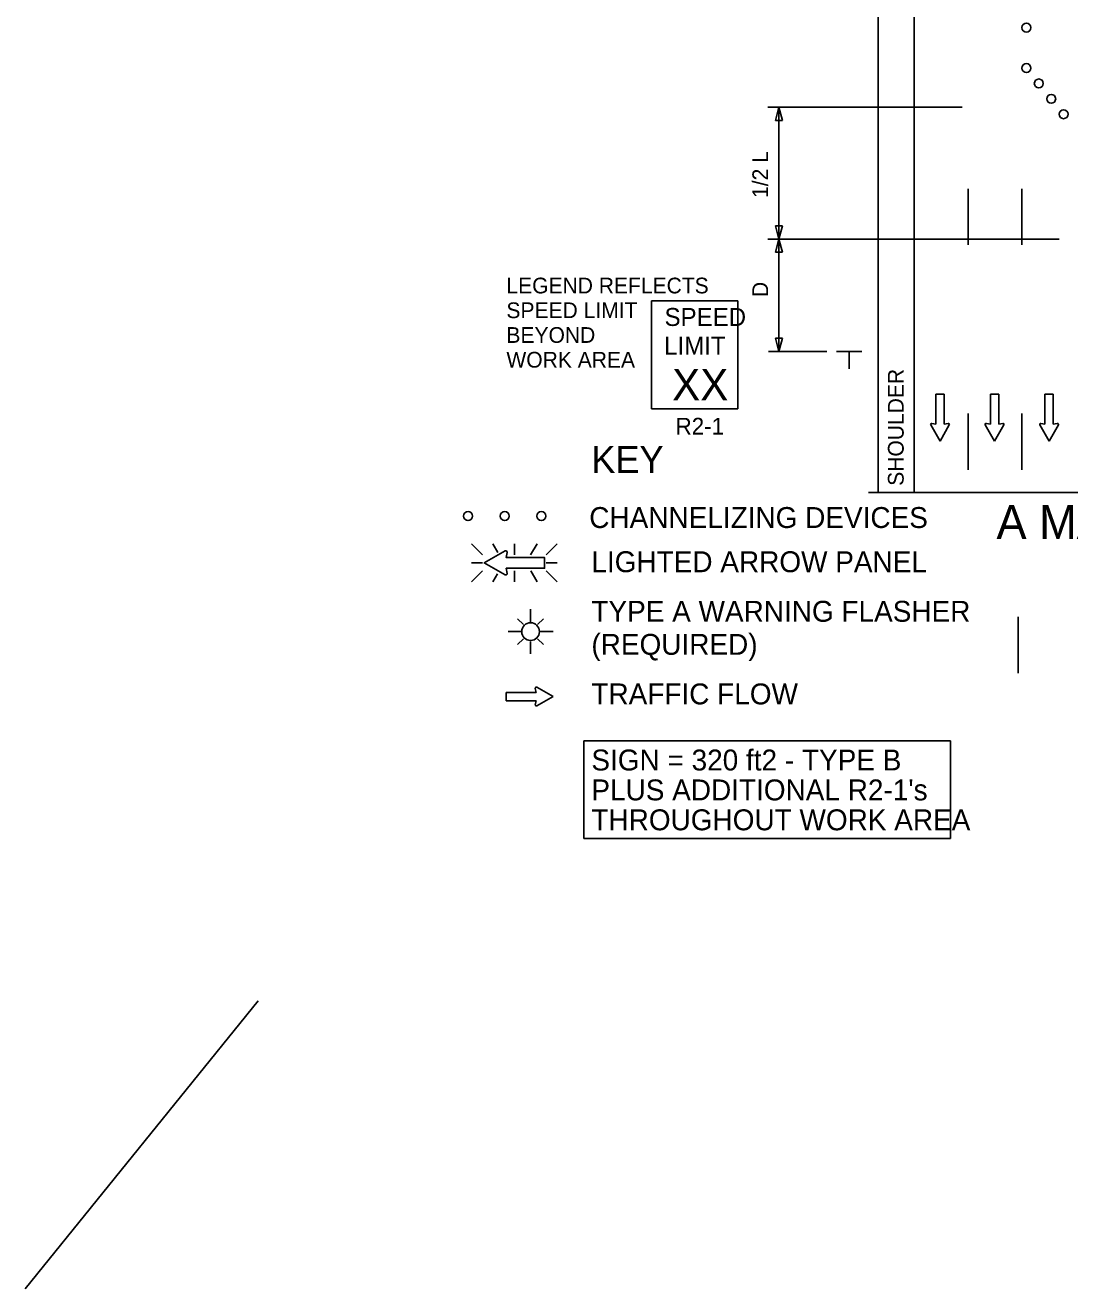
# Model space of a CAD drawing. Extents: x 16544 to 19504, y 5662 to 6909.
# Drawn here: x 16544 to 17009, y 5752 to 6314 of the extents above; entities that cross this region are included whole.
import ezdxf

# ---------------------------------------------------------------- set-up
doc = ezdxf.new("R2010")
doc.units = 0
for name, color, linetype in [('ALI_LEGAL_EX', 7, 'Continuous'), ('MT_SCRATCH_LEVEL_E', 7, 'Continuous'), ('PAVT_EDGE_EX', 7, 'Continuous'), ('TRAFFIC_SIGNS_PR', 7, 'Continuous'), ('TYPICAL_TEXT_DIMEN_EX', 7, 'Continuous'), ('TYPICAL_TEXT_DIMEN_PR', 7, 'Continuous')]:
    doc.layers.add(name, color=color, linetype=linetype)

msp = doc.modelspace()

# ---------------------------------------------------------------- linework, layer by layer
at = {"layer": 'ALI_LEGAL_EX'}
for points in [[(16963.46, 6241.23), (16963.46, 6216.23)], [(16987.46, 6241.23), (16987.46, 6216.23)], [(16963.46, 6141.23), (16963.46, 6116.23)], [(16987.46, 6141.23), (16987.46, 6116.23)]]:
    msp.add_lwpolyline(points, dxfattribs=at)
at = {"layer": 'MT_SCRATCH_LEVEL_E'}
for p, q in [((16952.87, 6149.79), (16949.13, 6149.79)), ((16949.13, 6149.79), (16949.13, 6136.54)), ((16952.87, 6149.79), (16949.13, 6149.79)), ((16949.13, 6149.79), (16949.13, 6136.54)), ((16952.87, 6136.54), (16952.87, 6149.79)), ((16952.87, 6136.54), (16952.87, 6149.79)), ((16977.13, 6149.79), (16973.39, 6149.79)), ((16973.39, 6149.79), (16973.39, 6136.54)), ((16977.13, 6149.79), (16973.39, 6149.79)), ((16973.39, 6149.79), (16973.39, 6136.54)), ((16977.13, 6136.54), (16977.13, 6149.79)), ((16977.13, 6136.54), (16977.13, 6149.79)), ((17001.39, 6149.79), (16997.64, 6149.79)), ((16997.64, 6149.79), (16997.64, 6136.54)), ((17001.39, 6149.79), (16997.64, 6149.79)), ((16997.64, 6149.79), (16997.64, 6136.54)), ((17001.39, 6136.54), (17001.39, 6149.79)), ((17001.39, 6136.54), (17001.39, 6149.79)), ((16946.87, 6136.17), (16951.02, 6128.93)), ((16946.87, 6136.17), (16951.02, 6128.93)), ((16949.13, 6136.54), (16947.35, 6136.85)), ((16949.13, 6136.54), (16947.35, 6136.85)), ((16951.02, 6128.93), (16955.13, 6136.17)), ((16951.02, 6128.93), (16955.13, 6136.17)), ((16954.65, 6136.85), (16952.87, 6136.54)), ((16954.65, 6136.85), (16952.87, 6136.54)), ((16971.13, 6136.17), (16975.28, 6128.93)), ((16971.13, 6136.17), (16975.28, 6128.93)), ((16973.39, 6136.54), (16971.61, 6136.85)), ((16973.39, 6136.54), (16971.61, 6136.85)), ((16975.28, 6128.93), (16979.39, 6136.17)), ((16975.28, 6128.93), (16979.39, 6136.17)), ((16978.91, 6136.85), (16977.13, 6136.54)), ((16978.91, 6136.85), (16977.13, 6136.54)), ((16995.39, 6136.17), (16999.53, 6128.93)), ((16995.39, 6136.17), (16999.53, 6128.93)), ((16997.64, 6136.54), (16995.87, 6136.85)), ((16997.64, 6136.54), (16995.87, 6136.85)), ((16999.53, 6128.93), (17003.64, 6136.17)), ((16999.53, 6128.93), (17003.64, 6136.17)), ((17003.16, 6136.85), (17001.39, 6136.54)), ((17003.16, 6136.85), (17001.39, 6136.54)), ((16778.89, 6015.35), (16771.65, 6019.46)), ((16778.89, 6015.35), (16771.65, 6019.46)), ((16771.28, 6017.2), (16758.03, 6017.2)), ((16758.03, 6017.2), (16758.03, 6013.46)), ((16771.28, 6017.2), (16758.03, 6017.2)), ((16758.03, 6017.2), (16758.03, 6013.46)), ((16770.97, 6018.98), (16771.28, 6017.2)), ((16770.97, 6018.98), (16771.28, 6017.2)), ((16771.65, 6011.21), (16778.89, 6015.35)), ((16771.65, 6011.21), (16778.89, 6015.35)), ((16758.03, 6013.46), (16771.28, 6013.46)), ((16758.03, 6013.46), (16771.28, 6013.46)), ((16771.28, 6013.46), (16770.97, 6011.69)), ((16771.28, 6013.46), (16770.97, 6011.69))]:
    msp.add_line(p, q, dxfattribs=at)
for centre, start, end in [((16947.28, 6136.39), 80.0362, 209.7731), ((16947.28, 6136.39), 80.0362, 209.7731), ((16954.72, 6136.39), 330.4248, 99.9638), ((16954.72, 6136.39), 330.4248, 99.9638), ((16971.54, 6136.39), 80.0362, 209.7731), ((16971.54, 6136.39), 80.0362, 209.7731), ((16978.98, 6136.39), 330.4248, 99.9638), ((16978.98, 6136.39), 330.4248, 99.9638), ((16995.8, 6136.39), 80.0362, 209.7731), ((16995.8, 6136.39), 80.0362, 209.7731), ((17003.24, 6136.39), 330.4248, 99.9638), ((17003.24, 6136.39), 330.4248, 99.9638), ((16771.43, 6019.06), 60.4248, 189.9638), ((16771.43, 6019.06), 60.4248, 189.9638), ((16771.43, 6011.62), 170.0362, 299.7731), ((16771.43, 6011.62), 170.0362, 299.7731)]:
    msp.add_arc(centre, 0.463, start, end, dxfattribs=at)
at = {"layer": 'PAVT_EDGE_EX'}
for p, q in [((16923.46, 6880.02), (16923.46, 6106.05)), ((16939.46, 6880.02), (16939.46, 6106.05))]:
    msp.add_line(p, q, dxfattribs=at)
msp.add_lwpolyline([(16985.78, 6025.74), (16985.78, 6050.74)], dxfattribs=at)
msp.add_lwpolyline([(16985.78, 6025.74), (16985.78, 6050.74)], dxfattribs=at)
at = {"layer": 'TRAFFIC_SIGNS_PR'}
for p, q in [((16822.7, 6191.31), (16861.1, 6191.31)), ((16822.7, 6143.31), (16822.7, 6191.31)), ((16861.1, 6143.31), (16861.1, 6191.31)), ((16822.7, 6143.31), (16861.1, 6143.31)), ((16742.57, 6083.29), (16747.51, 6078.36)), ((16754.34, 6079.47), (16752.13, 6083.29)), ((16761.66, 6078.36), (16761.66, 6083.29)), ((16768.89, 6078.36), (16771.74, 6083.29)), ((16775.81, 6078.36), (16780.74, 6083.3)), ((16747.51, 6074.8), (16742.57, 6074.8)), ((16742.57, 6066.31), (16747.51, 6071.25)), ((16752.09, 6066.31), (16754.2, 6069.97)), ((16761.66, 6071.25), (16761.66, 6066.31)), ((16771.79, 6066.31), (16768.94, 6071.25)), ((16775.81, 6074.8), (16780.74, 6074.8)), ((16775.81, 6071.25), (16780.74, 6066.31)), ((16768.86, 6048.64), (16768.86, 6054.26)), ((16768.86, 6048.64), (16768.86, 6054.26)), ((16765.72, 6047.34), (16763.09, 6049.97)), ((16765.72, 6047.34), (16763.09, 6049.97)), ((16772, 6047.34), (16774.63, 6049.97)), ((16772, 6047.34), (16774.63, 6049.97)), ((16764.92, 6044.2), (16758.88, 6044.2)), ((16764.92, 6044.2), (16758.88, 6044.2)), ((16772.8, 6044.2), (16778.89, 6044.2)), ((16772.8, 6044.2), (16778.89, 6044.2)), ((16765.72, 6041.07), (16763.09, 6038.43)), ((16765.72, 6041.07), (16763.09, 6038.43)), ((16768.86, 6034.26), (16768.86, 6039.76)), ((16768.86, 6034.26), (16768.86, 6039.76)), ((16772, 6041.06), (16774.63, 6038.43)), ((16772, 6041.06), (16774.63, 6038.43))]:
    msp.add_line(p, q, dxfattribs=at)
for points in [[(16757.58, 6080.08), (16748.29, 6074.8), (16757.59, 6069.48)], [(16758.46, 6070.11), (16758.06, 6072.38), (16775.07, 6072.38), (16775.07, 6077.18), (16758.06, 6077.18), (16758.46, 6079.46)]]:
    msp.add_lwpolyline(points, dxfattribs=at)
for centre, radius in [((16989.46, 6312.87), 2), ((16989.46, 6294.87), 2), ((16989.46, 6294.87), 2), ((16989.46, 6294.87), 2), ((16994.96, 6288.04), 2), ((17000.46, 6281.21), 2), ((17005.96, 6274.38), 2), ((16741.08, 6095.64), 2), ((16757.38, 6095.64), 2), ((16773.68, 6095.64), 2), ((16768.86, 6044.2), 3.94), ((16768.86, 6044.2), 3.94)]:
    msp.add_circle(centre, radius, dxfattribs=at)
for centre, radius, start, end in [((16757.87, 6079.56), 0.598, 350.7308, 118.8916), ((16757.87, 6070.01), 0.597, 241.4833, 9.9593)]:
    msp.add_arc(centre, radius, start, end, dxfattribs=at)
at = {"layer": 'TYPICAL_TEXT_DIMEN_EX'}
msp.add_lwpolyline([(16792.58, 5995.57), (16955.61, 5995.57), (16955.61, 5952.2), (16792.58, 5952.2)], close=True, dxfattribs=at)
at = {"layer": 'TYPICAL_TEXT_DIMEN_PR'}
for p, q in [((16874.36, 6277.47), (16960.87, 6277.47)), ((16877.79, 6271.61), (16879.36, 6277.47)), ((16879.36, 6218.83), (16879.36, 6277.47)), ((16879.36, 6277.47), (16880.93, 6271.61)), ((16879.36, 6271.61), (16877.79, 6271.61)), ((16880.93, 6271.61), (16879.36, 6271.61)), ((16879.36, 6218.83), (16877.79, 6224.69)), ((16877.79, 6224.69), (16879.36, 6224.69)), ((16879.36, 6224.69), (16880.93, 6224.69)), ((16880.93, 6224.69), (16879.36, 6218.83)), ((16874.36, 6218.83), (17003.99, 6218.83)), ((16877.79, 6212.97), (16879.36, 6218.83)), ((16879.36, 6168.83), (16879.36, 6218.83)), ((16879.36, 6218.83), (16880.93, 6212.97)), ((16879.36, 6212.97), (16877.79, 6212.97)), ((16880.93, 6212.97), (16879.36, 6212.97)), ((16879.36, 6168.83), (16877.79, 6174.69)), ((16877.79, 6174.69), (16879.36, 6174.69)), ((16879.36, 6174.69), (16880.93, 6174.69)), ((16880.93, 6174.69), (16879.36, 6168.83)), ((16900.73, 6168.83), (16874.73, 6168.83)), ((16904.98, 6168.83), (16916.23, 6168.83)), ((16910.6, 6168.83), (16910.6, 6161.04)), ((16919.16, 6106.05), (17127.76, 6106.05)), ((16647.75, 5880), (16544.08, 5751.92))]:
    msp.add_line(p, q, dxfattribs=at)

# ---------------------------------------------------------------- texts
at = {"layer": 'TRAFFIC_SIGNS_PR'}
for s, height, p in [('SPEED', 8, (16828.46, 6180.18)), ('LIMIT', 8, (16828.3, 6167.38)), ('XX', 14.031, (16831.81, 6147.07)), ('R2-1', 7.44, (16833.37, 6131.87))]:
    msp.add_text(s, height=height, dxfattribs=at).set_placement(p)
at = {"layer": 'TYPICAL_TEXT_DIMEN_EX'}
for s, height, p in [('KEY', 12, (16795.92, 6114.75)), ('CHANNELIZING DEVICES', 9.3, (16794.97, 6090.31)), ('LIGHTED ARROW PANEL', 9.3, (16795.92, 6070.65)), ('TYPE A WARNING FLASHER', 9.3, (16795.92, 6048.6)), ('(REQUIRED)', 9.3, (16795.92, 6033.9)), ('TRAFFIC FLOW', 9.3, (16795.92, 6011.85)), ('SIGN = 320 ft2 - TYPE B', 9.3, (16795.92, 5982.45)), ("PLUS ADDITIONAL R2-1's", 9.3, (16795.92, 5969.15)), ('THROUGHOUT WORK AREA', 9.3, (16795.92, 5955.85))]:
    msp.add_text(s, height=height, dxfattribs=at).set_placement(p)
at = {"layer": 'TYPICAL_TEXT_DIMEN_PR'}
for s, p in [('1/2 L', (16874.53, 6237.12)), ('D', (16874.53, 6193.05)), ('SHOULDER', (16934.84, 6109.07))]:
    msp.add_text(s, height=7, rotation=90, dxfattribs=at).set_placement(p)
for s, height, p in [('LEGEND REFLECTS', 7, (16758.12, 6194.66)), ('SPEED LIMIT', 7, (16758.12, 6183.66)), ('BEYOND', 7, (16758.12, 6172.66)), ('WORK AREA', 7, (16758.12, 6161.66)), ('A MATCH A', 15, (16976.13, 6085.48))]:
    msp.add_text(s, height=height, dxfattribs=at).set_placement(p)

doc.saveas('drawing.dxf')
